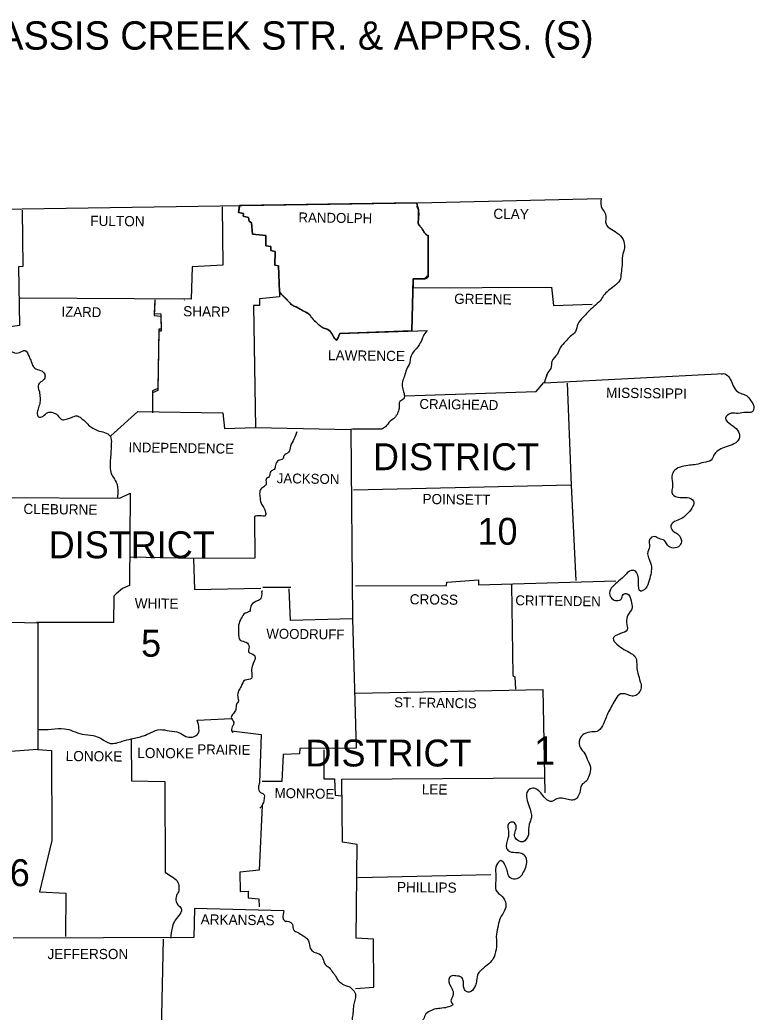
# Model space of a CAD drawing. Extents: x 152 to 3426, y 67 to 2142.
# Drawn here: x 2999.8 to 3303.9, y 1623.7 to 2035 of the extents above; entities that cross this region are included whole.
import ezdxf

# ---------------------------------------------------------------- set-up
doc = ezdxf.new("R2010")
doc.units = 0
for name, color, linetype in [('R_Border', 7, 'Continuous'), ('R_Grid', 7, 'Continuous'), ('S_AREA_CALC', 7, 'Continuous'), ('S_MISC_BOUNDARY', 7, 'Continuous')]:
    doc.layers.add(name, color=color, linetype=linetype)

msp = doc.modelspace()

# ---------------------------------------------------------------- linework, layer by layer
at = {"layer": 'S_AREA_CALC'}
for p, q in [((3090.74, 1958.01), (3163.96, 1959.15)), ((3168.84, 1945.36), (3168.84, 1928.38)), ((3216.98, 1884.51), (3218.15, 1888.13)), ((3217.27, 1885.68), (3218.45, 1888.52)), ((3100.35, 1799.78), (3112, 1799.78))]:
    msp.add_line(p, q, dxfattribs=at)
for points in [[(2703.71, 1956.42), (2861.92, 1956.32), (3000.75, 1956.61), (3164.54, 1959.16), (3240.46, 1960.92)], [(3107.24, 1922.16), (3106.91, 1932.94), (3105.34, 1933.23), (3105.44, 1938.9), (3103.68, 1939.39), (3103.68, 1941.06), (3101.63, 1941.35), (3101.63, 1945.56), (3096.05, 1946.15), (3095.75, 1950.84), (3094.68, 1951.53), (3094.48, 1953.09), (3092.23, 1953.58), (3092.33, 1954.76), (3090.37, 1955.05), (3090.74, 1958.01)], [(3000.75, 1956.03), (3000.95, 1932.74), (2999.28, 1932.64), (2999.58, 1908.28), (2992.73, 1907.3), (2993.32, 1900.75), (2995.66, 1897.71), (2995.47, 1889.98), (2982.16, 1889.5), (2981.67, 1877.56), (2969.54, 1877.17), (2968.95, 1862.69), (2969.64, 1861.51), (2969.93, 1838.42), (2990.87, 1837.05), (2990.58, 1785.49), (3007.21, 1785), (3007.21, 1732.56), (2994.1, 1731.58), (2993.12, 1720.04), (2971.11, 1719.94)], [(3083.62, 1957.49), (3083.82, 1933.23), (3071.1, 1932.55), (3070.71, 1919.24), (2999.97, 1919.63)], [(3090.67, 1957.4), (3090.37, 1955.05), (3092.33, 1954.76), (3092.23, 1953.58), (3094.48, 1953.09), (3094.68, 1951.53), (3095.75, 1950.84), (3096.05, 1946.15), (3101.63, 1945.56), (3101.63, 1941.35), (3103.68, 1941.06), (3103.68, 1939.39), (3105.44, 1938.9), (3105.34, 1933.23), (3106.91, 1932.94), (3107.3, 1920.12), (3098.98, 1919.34), (3099.08, 1916.6), (3096.54, 1916.5), (3097.42, 1866.01), (3136.85, 1865.13), (3137.53, 1786.66), (3111.8, 1785.98), (3111.31, 1799.19)], [(3168.84, 1945.66), (3168.84, 1929.12)], [(3162.68, 1927.56), (3162.16, 1906), (3132.25, 1904.95)], [(3162.19, 1907.11), (3162.68, 1927.56), (3162.68, 1923.94), (3219.91, 1924.23), (3220.7, 1916.6), (3236.84, 1917.18)], [(3055.64, 1918.95), (3055.44, 1913.27), (3058.18, 1913.07), (3058.28, 1906.81), (3057.3, 1906.81), (3056.91, 1882.16), (3054.66, 1881.18), (3054.66, 1872.96)], [(3055.64, 1918.06), (3055.44, 1912.39), (3058.18, 1912.19), (3058.28, 1905.93), (3057.3, 1905.93), (3056.91, 1881.28), (3054.66, 1880.3), (3054.66, 1872.08)], [(3067.87, 1918.75), (3067.97, 1918.85)], [(3132.25, 1904.95), (3168.55, 1906.23)], [(3216.98, 1884.51), (3291.24, 1888.32)], [(3159.25, 1879.12), (3213.55, 1880.89), (3216.78, 1884.6)], [(3226.37, 1884.41), (3228.04, 1842.04), (3229.99, 1802.61)], [(3037.44, 1862.49), (3048.6, 1872.57), (3083.82, 1872.08), (3084.5, 1865.52), (3097.32, 1866.01)], [(3149.67, 1865.33), (3137.73, 1865.33), (3136.85, 1865.13)], [(2990.87, 1837.05), (3041.16, 1836.76), (3045.46, 1838.81), (3045.17, 1800.56), (3042.24, 1799.29), (3039.59, 1797.04), (3038.71, 1796.16), (3038.62, 1785.2), (3006.62, 1785.2)], [(3228.04, 1842.04), (3137.92, 1839.99)], [(3096.93, 1829.03), (3097.12, 1811.81), (3071.69, 1811.71), (3045.56, 1812.2)], [(3071.69, 1811.71), (3072.08, 1798.89), (3099.57, 1799.38)], [(3138.71, 1800.36), (3176.47, 1800.56), (3176.57, 1801.93), (3189.68, 1802.91), (3189.68, 1800.85), (3246.63, 1802.42)], [(3100.35, 1798.11), (3099.86, 1798.01)], [(3203.38, 1800.85), (3203.87, 1763.18), (3204.75, 1762.6), (3205.04, 1757.51)], [(3137.53, 1786.66), (3139, 1733.05), (3115.71, 1732.95), (3115.62, 1730.8), (3108.87, 1730.41), (3108.28, 1719.25), (3100.06, 1719.25)], [(3138.71, 1755.85), (3216.39, 1757.41)], [(3216.39, 1757.41), (3217.18, 1714.56)], [(3073.25, 1744.69), (3087.44, 1745.38)], [(3087.44, 1740.29), (3099.67, 1738.72), (3098.98, 1718.76)], [(3045.86, 1737.06), (3046.05, 1719.55), (3059.85, 1719.25), (3059.95, 1681.68)], [(3007.21, 1732.56), (3012.88, 1732.17), (3012.98, 1694.79), (3007.89, 1673.56), (3018.75, 1673.07), (3018.66, 1655.07)], [(3125.69, 1732.46), (3125.6, 1720.33), (3130.1, 1720.33), (3130.29, 1713.58), (3133.13, 1713.28)], [(3138.71, 1633.54), (3146.34, 1634.03), (3146.24, 1653.9), (3139.1, 1654.38), (3139.49, 1693.23), (3133.33, 1694.11), (3133.13, 1720.23), (3216.59, 1720.82)], [(3100.06, 1709.37), (3098.89, 1682.56), (3090.86, 1681.68), (3091.06, 1673.76), (3094.29, 1673.85), (3094.39, 1671.11), (3098.79, 1670.63), (3098.89, 1667.4)], [(3139.69, 1679.43), (3194.87, 1680.8)], [(3109.06, 1665.64), (3072.08, 1666.61), (3071.88, 1654.58), (2997.03, 1654.29)], [(3059.06, 1653.99), (3058.28, 1616.13), (3071.88, 1615.05)]]:
    msp.add_lwpolyline(points, dxfattribs=at)
for points in [[(3163.96, 1959.15), (3164.16, 1958.7), (3164.34, 1958.24), (3164.65, 1957.32), (3164.85, 1956.38), (3164.88, 1956.15), (3164.91, 1955.91), (3164.93, 1955.44), (3164.92, 1954.78), (3164.89, 1954.12), (3164.85, 1953.46), (3164.83, 1952.8), (3164.82, 1952.49), (3164.77, 1951.57), (3164.76, 1950.96), (3164.78, 1950.66), (3164.8, 1950.5), (3164.82, 1950.43), (3164.83, 1950.35), (3164.91, 1950.11), (3164.96, 1949.99), (3165.03, 1949.88), (3165.19, 1949.67), (3165.37, 1949.48), (3165.76, 1949.09), (3165.94, 1948.9), (3166.1, 1948.69), (3166.42, 1948.18), (3166.72, 1947.66), (3167.03, 1947.14), (3167.2, 1946.88), (3167.37, 1946.63), (3167.59, 1946.39), (3167.83, 1946.16), (3168.08, 1945.96), (3168.84, 1945.36)], [(3164.05, 1957.89), (3164.93, 1955.44), (3164.83, 1952.8), (3164.83, 1950.35), (3166.1, 1948.69), (3167.37, 1946.63), (3168.35, 1945.75)], [(3240.46, 1960.92), (3240.95, 1956.61), (3242.32, 1954.36), (3242.52, 1950.25), (3244.18, 1948.49), (3247.02, 1946.73), (3249.56, 1943.89), (3250.15, 1940.57), (3249.36, 1937.14), (3249.17, 1933.33), (3248.78, 1930), (3248.19, 1926.97), (3245.84, 1924.52), (3243.59, 1922.76), (3241.54, 1920.71), (3240.07, 1918.55), (3237.53, 1916.21), (3234.98, 1913.76), (3232.93, 1911.61), (3230.87, 1908.87), (3229.89, 1905.83), (3227.64, 1903.68), (3225.88, 1901.73), (3223.53, 1899.08), (3222.36, 1896.44), (3220.11, 1893.41), (3219.62, 1890.47), (3218.15, 1888.13), (3218.06, 1887.73)], [(3168.45, 1928.83), (3167.18, 1927.56), (3164.73, 1927.56), (3162.68, 1927.56)], [(3168.84, 1928.38), (3168.66, 1928.21), (3168.47, 1928.05), (3168.07, 1927.79), (3167.63, 1927.62), (3167.41, 1927.57), (3167.29, 1927.56), (3167.18, 1927.56), (3164.73, 1927.56), (3162.68, 1927.56)], [(3132.25, 1904.95), (3132.1, 1904.53), (3131.93, 1904.04), (3131.55, 1903.06), (3131.12, 1902.36), (3130.9, 1902.23), (3130.79, 1902.24), (3130.68, 1902.31), (3130.64, 1902.35), (3130.59, 1902.4), (3130.5, 1902.5), (3130.32, 1902.72), (3129.95, 1903.24), (3129.58, 1903.81), (3129.4, 1904.1), (3129.22, 1904.37), (3128.95, 1904.79), (3128.69, 1905.21), (3128.43, 1905.63), (3128.14, 1906.03), (3127.82, 1906.34), (3127.45, 1906.57), (3126.6, 1906.9), (3125.71, 1907.18), (3124.91, 1907.6), (3124.39, 1907.99), (3123.86, 1908.4), (3123.35, 1908.82), (3122.86, 1909.26), (3121.81, 1910.27), (3120.8, 1911.31), (3120.61, 1911.54), (3120.44, 1911.78), (3120.11, 1912.29), (3119.77, 1912.77), (3119.33, 1913.17), (3119.2, 1913.26), (3119.06, 1913.34), (3118.22, 1913.78), (3117.65, 1914.05), (3117.08, 1914.35), (3115.81, 1915.08), (3114.54, 1915.81), (3114, 1916.08), (3113.44, 1916.31), (3112.89, 1916.56), (3112.39, 1916.89), (3112.26, 1917), (3112.14, 1917.11), (3111.9, 1917.33), (3111.44, 1917.8), (3110.53, 1918.75), (3108.87, 1920.44), (3107.24, 1922.16)], [(3108.38, 1921), (3110.53, 1918.75), (3112.39, 1916.89), (3114.54, 1915.81), (3117.08, 1914.35), (3119.33, 1913.17), (3120.8, 1911.31), (3122.86, 1909.26), (3124.91, 1907.6), (3128.14, 1906.03), (3129.22, 1904.37), (3130.68, 1902.31), (3132.25, 1904.95)], [(3168.25, 1906.13), (3166.79, 1903.78), (3165.61, 1901.04), (3163.26, 1897.91), (3161.5, 1894.88), (3161.21, 1892.82), (3159.84, 1890.08), (3159.06, 1887.34), (3158.18, 1884.99), (3158.18, 1882.55), (3158.86, 1880.1), (3158.67, 1877.85), (3157.2, 1876.78), (3156.81, 1873.94), (3156.22, 1871.98), (3154.95, 1870.03), (3153.09, 1868.56), (3151.13, 1866.31), (3149.67, 1865.33)], [(2995.66, 1897.71), (2999.58, 1897.03), (3001.93, 1897.91), (3003.59, 1895.37), (3004.47, 1893.41), (3005.94, 1890.57), (3008.29, 1889.69), (3010.05, 1888.13), (3010.05, 1886.46), (3008.48, 1884.9), (3007.31, 1883.33), (3007.7, 1881.47), (3008.09, 1878.93), (3008.09, 1876.48), (3007.5, 1874.23), (3007.01, 1872.18), (3007.5, 1870.42), (3009.36, 1870.71), (3011.32, 1872.18), (3013.37, 1872.18), (3015.33, 1871.1), (3017.38, 1869.24), (3019.44, 1869.63), (3021.1, 1870.12), (3023.45, 1870.81), (3025.11, 1869.93), (3026.58, 1868.75), (3028.34, 1866.89), (3030.01, 1865.72), (3032.16, 1864.64), (3034.8, 1863.96), (3037.25, 1862.3), (3037.64, 1859.46), (3037.54, 1857.01), (3037.34, 1853.98), (3037.15, 1850.65), (3037.44, 1847.42), (3038.52, 1845.27), (3039.89, 1842.73), (3040.28, 1840.38), (3040.18, 1836.66)], [(3290.16, 1888.22), (3291.24, 1888.32), (3294.57, 1884.8), (3296.03, 1881.86), (3298.19, 1880.2), (3300.63, 1879.32), (3302.49, 1877.07), (3303.76, 1874.62), (3303.08, 1872.47), (3300.34, 1872.28), (3297.31, 1871.79), (3294.37, 1871.88), (3292.02, 1869.93), (3294.18, 1867.29), (3297.01, 1864.84), (3297.8, 1862.2), (3296.23, 1859.65), (3293.1, 1858.28), (3290.07, 1857.11), (3287.33, 1854.76), (3286.05, 1852.51), (3283.02, 1851.53), (3279.89, 1850.65), (3277.15, 1850.36), (3274.02, 1849.77), (3270.99, 1848.3), (3269.72, 1845.76), (3270.11, 1842.14), (3270.01, 1838.32), (3273.24, 1837.05), (3276.08, 1836.95), (3278.81, 1835.49), (3278.52, 1833.33), (3276.47, 1830.6), (3274.02, 1828.44), (3271.57, 1827.37), (3269.32, 1825.31), (3270.11, 1823.26), (3272.16, 1821.89), (3273.63, 1819.64), (3273.43, 1817.58), (3271.09, 1816.11), (3268.54, 1816.7), (3266.68, 1819.15), (3264.53, 1819.93), (3262.67, 1820.81), (3260.52, 1819.54), (3260.52, 1816.7), (3259.74, 1813.67), (3260.42, 1811.42), (3261.3, 1808.29), (3261.2, 1805.94), (3260.42, 1802.61), (3258.76, 1799.19), (3256.8, 1798.11), (3256.02, 1801.83), (3255.63, 1804.86), (3254.45, 1806.62), (3252.89, 1806.72), (3250.83, 1805.25), (3248.58, 1803), (3245.74, 1800.56), (3244.08, 1798.11), (3244.96, 1795.08), (3247.11, 1794.3), (3248.78, 1794.88), (3249.66, 1796.84), (3251.32, 1797.13), (3252.89, 1794.1)], [(3114.44, 1864.25), (3113.27, 1861.22), (3111.9, 1858.28), (3111.02, 1855.74), (3109.16, 1854.27), (3108.57, 1852.9), (3106.91, 1852.32), (3105.64, 1850.36), (3105.05, 1848.6), (3103.68, 1847.82), (3103, 1845.66), (3101.72, 1844.49), (3101.82, 1842.53), (3100.35, 1841.16), (3099.18, 1839.6), (3099.18, 1837.44), (3099.67, 1834.61), (3100.65, 1832.94), (3101.53, 1830.79), (3101.43, 1829.42), (3098.98, 1829.42), (3096.93, 1829.03)], [(3099.86, 1798.01), (3099.37, 1794.79), (3097.52, 1793.91), (3095.36, 1791.75), (3094.87, 1789.8), (3093.11, 1789.01), (3091.45, 1786.96), (3090.37, 1784.12), (3090.37, 1781.19), (3091.06, 1777.86), (3093.5, 1776.98), (3094.68, 1775.02), (3094.48, 1772.97), (3096.83, 1771.6), (3097.22, 1770.42), (3096.83, 1769.15), (3095.75, 1765.53), (3095.85, 1763.09), (3095.66, 1762.01), (3093.02, 1761.32), (3091.45, 1758.68), (3090.37, 1756.82), (3089.98, 1754.38), (3090.28, 1752.62), (3089.49, 1751.25), (3089.2, 1749.19), (3088.22, 1747.43), (3087.34, 1745.77), (3088.32, 1743.81), (3088.03, 1742.44), (3087.44, 1740.29), (3087.93, 1739.6)], [(3252.89, 1794.1), (3253.28, 1791.26), (3251.62, 1788.23), (3251.03, 1785.2), (3251.32, 1782.16), (3248.19, 1780.5), (3245.45, 1778.54), (3247.02, 1776.2), (3249.95, 1774.04), (3252.89, 1772.38), (3254.75, 1770.72), (3255.24, 1766.71), (3255.72, 1764.16), (3256.7, 1760.64), (3257.09, 1758.19), (3255.33, 1755.26), (3253.28, 1754.67), (3251.13, 1755.36), (3248.58, 1755.55), (3246.53, 1753.59), (3245.06, 1750.86), (3243.59, 1748.12), (3242.52, 1745.77), (3241.44, 1743.22), (3239.29, 1740.29), (3236.65, 1739.8), (3233.51, 1739.02), (3231.66, 1736.86), (3231.95, 1733.24), (3233.71, 1730.8), (3235.08, 1727.76), (3236.06, 1725.12), (3235.57, 1721.8), (3234.2, 1719.35), (3232.44, 1717.88), (3231.66, 1714.75), (3230.38, 1712.4), (3229.21, 1711.62), (3226.86, 1711.82), (3224.32, 1712.31), (3222.16, 1712.11), (3220.11, 1711.03), (3218.06, 1711.72), (3215.9, 1714.07), (3214.14, 1715.83), (3212.19, 1716.51), (3210.13, 1715.44), (3209.74, 1712.21), (3210.72, 1708.88), (3211.6, 1704.38), (3210.72, 1701.64), (3210.42, 1697.14)], [(3007.4, 1740.78), (3012.88, 1740.97), (3018.26, 1741.17), (3021.69, 1740.19), (3025.6, 1738.92), (3030.2, 1738.33), (3033.43, 1737.06), (3037.25, 1735.1), (3042.14, 1735.98), (3045.95, 1736.96), (3050.94, 1738.23), (3054.17, 1739.6), (3057.89, 1740.78), (3061.61, 1740.29), (3065.82, 1739.51), (3068.46, 1737.94), (3073.25, 1738.63), (3073.25, 1744.69)], [(3098.98, 1718.76), (3098.59, 1716.81), (3099.37, 1714.75), (3100.74, 1714.07), (3100.94, 1712.11), (3100.45, 1710.15), (3100.06, 1709.37), (3099.18, 1708.2)], [(3210.42, 1697.14), (3208.17, 1694.3), (3204.85, 1696.06), (3204.85, 1698.41), (3205.34, 1700.86), (3204.16, 1702.42), (3202.11, 1701.74), (3202.11, 1698.71), (3201.91, 1695.77), (3201.32, 1691.56), (3202.69, 1690.29), (3205.83, 1689.9), (3208.08, 1689.31), (3209.45, 1687.06), (3209.35, 1684.32), (3208.27, 1681.68), (3206.71, 1679.53), (3204.26, 1678.75), (3202.3, 1680.02), (3201.52, 1682.56), (3200.64, 1684.81), (3198.98, 1686.48), (3197.22, 1684.62), (3196.82, 1681.19), (3196.92, 1678.26), (3196.92, 1674.25), (3199.47, 1671.6), (3201.03, 1668.57), (3200.54, 1665.83), (3198.68, 1662.6), (3197.9, 1659.77), (3197.12, 1655.95), (3197.22, 1651.74), (3196.53, 1647.63), (3195.16, 1644.89), (3192.62, 1642.64), (3190.95, 1641.18), (3189.58, 1639.71), (3188.9, 1636.77), (3188.41, 1634.72), (3186.55, 1632.27), (3185.08, 1632.08), (3183.91, 1633.05), (3183.52, 1634.72), (3183.52, 1636.38), (3182.74, 1638.04), (3180.29, 1638.73), (3178.33, 1638.63), (3177.45, 1637.26), (3178.72, 1633.45), (3179.21, 1631), (3178.53, 1627.67), (3178.92, 1627.28), (3175.4, 1625.42), (3172.56, 1625.13), (3170.21, 1624.44), (3167.96, 1622.98), (3166.88, 1620.82), (3165.32, 1619.06), (3163.95, 1617.4), (3162.09, 1616.62), (3160.04, 1617.01), (3157.3, 1617.3), (3155.73, 1615.35), (3156.22, 1612.51), (3158.08, 1610.85), (3160.82, 1610.06), (3163.66, 1610.26), (3166.4, 1610.55), (3168.94, 1609.18), (3168.45, 1606.54), (3166, 1605.27), (3162.38, 1604.88), (3159.45, 1605.17), (3155.93, 1604.39), (3154.17, 1602.14), (3155.14, 1598.71), (3158.96, 1597.34), (3160.72, 1594.11), (3160.82, 1591.08), (3159.55, 1587.07), (3157.79, 1585.21), (3154.36, 1584.43), (3151.72, 1583.94), (3151.33, 1579.44), (3150.15, 1577.19), (3148.1, 1576.5), (3145.16, 1577.97), (3143.4, 1578.66), (3141.25, 1579.63), (3138.51, 1581.3), (3136.46, 1581), (3137.04, 1576.7), (3137.24, 1576.5), (3139.59, 1573.27), (3141.94, 1570.73), (3143.01, 1567.7)], [(3059.95, 1681.68), (3062.39, 1680.02), (3064.93, 1678.06), (3065.62, 1675.42), (3065.42, 1673.56), (3064.64, 1672), (3064.45, 1669.55), (3065.62, 1667.79), (3066.7, 1666.32), (3065.62, 1663.68), (3063.76, 1661.23), (3062.78, 1658.49), (3062.1, 1654.38)], [(3109.06, 1665.64), (3109.35, 1661.62), (3111.7, 1661.04), (3112.68, 1659.96), (3113.17, 1657.71), (3114.83, 1656.73), (3117.08, 1655.36), (3118.45, 1654.38), (3119.43, 1652.82), (3120.02, 1650.27), (3121.58, 1648.61), (3123.74, 1647.83), (3125.3, 1645.97), (3126.28, 1643.33), (3127.85, 1642.15), (3129.41, 1640.1), (3130.19, 1639.22), (3131.56, 1636.87), (3132.93, 1635.7), (3133.91, 1635.01), (3135.48, 1634.52), (3137.43, 1633.25), (3138.71, 1631.29), (3138.71, 1629.83), (3138.22, 1627.58), (3137.83, 1625.23), (3137.63, 1622.59), (3137.43, 1620.24), (3138.32, 1618.28), (3137.83, 1615.35), (3136.85, 1613.78), (3136.75, 1611.63), (3136.46, 1608.4), (3136.07, 1606.54), (3135.18, 1603.51), (3133.91, 1601.94)]]:
    msp.add_spline(points, degree=3, dxfattribs=at)
at = {"layer": 'S_MISC_BOUNDARY'}
for p, q in [((3163.96, 1959.15), (3090.74, 1958.01)), ((3168.84, 1928.38), (3168.84, 1945.36))]:
    msp.add_line(p, q, dxfattribs=at)
for points in [[(3090.74, 1958.01), (3090.37, 1955.05), (3092.33, 1954.76), (3092.23, 1953.58), (3094.48, 1953.09), (3094.68, 1951.53), (3095.75, 1950.84), (3096.05, 1946.15), (3101.63, 1945.56), (3101.63, 1941.35), (3103.68, 1941.06), (3103.68, 1939.39), (3105.44, 1938.9), (3105.34, 1933.23), (3106.91, 1932.94), (3107.24, 1922.16)], [(3132.25, 1904.95), (3162.16, 1906), (3162.68, 1927.56)]]:
    msp.add_lwpolyline(points, dxfattribs=at)
for points in [[(3164.77, 1951.58), (3164.82, 1952.49), (3164.83, 1952.8), (3164.85, 1953.46), (3164.89, 1954.12), (3164.92, 1954.78), (3164.93, 1955.44), (3164.91, 1955.91), (3164.88, 1956.15), (3164.85, 1956.38), (3164.65, 1957.32), (3164.34, 1958.24), (3164.16, 1958.7), (3163.96, 1959.15)], [(3168.84, 1945.36), (3168.08, 1945.96), (3167.83, 1946.16), (3167.59, 1946.39), (3167.37, 1946.63), (3167.2, 1946.88), (3167.03, 1947.14), (3166.72, 1947.66), (3166.42, 1948.18), (3166.1, 1948.69), (3165.94, 1948.9), (3165.76, 1949.09), (3165.37, 1949.48), (3165.19, 1949.67), (3165.03, 1949.88), (3164.96, 1949.99), (3164.91, 1950.11), (3164.83, 1950.35), (3164.82, 1950.43), (3164.8, 1950.5), (3164.78, 1950.66), (3164.76, 1950.96), (3164.77, 1951.57), (3164.77, 1951.58)], [(3162.68, 1927.56), (3164.73, 1927.56), (3167.18, 1927.56), (3167.29, 1927.56), (3167.41, 1927.57), (3167.63, 1927.62), (3168.07, 1927.79), (3168.47, 1928.05), (3168.66, 1928.21), (3168.84, 1928.38)], [(3107.24, 1922.16), (3108.87, 1920.44), (3110.53, 1918.75), (3111.44, 1917.8), (3111.9, 1917.33), (3112.14, 1917.11), (3112.26, 1917), (3112.39, 1916.89), (3112.89, 1916.56), (3113.44, 1916.31), (3114, 1916.08), (3114.54, 1915.81), (3115.81, 1915.08), (3117.08, 1914.35), (3117.65, 1914.05), (3118.22, 1913.78), (3119.06, 1913.34), (3119.2, 1913.26), (3119.33, 1913.17), (3119.77, 1912.77), (3120.11, 1912.29), (3120.44, 1911.78), (3120.6, 1911.55)], [(3120.6, 1911.55), (3120.61, 1911.54), (3120.8, 1911.31), (3121.81, 1910.27), (3122.86, 1909.26), (3123.35, 1908.82), (3123.86, 1908.4), (3124.39, 1907.99), (3124.91, 1907.6), (3125.71, 1907.18), (3125.93, 1907.11), (3126.16, 1907.04), (3126.38, 1906.97), (3126.6, 1906.9), (3127.45, 1906.57), (3127.82, 1906.34), (3128.14, 1906.03), (3128.43, 1905.63), (3128.69, 1905.21), (3128.95, 1904.79), (3129.22, 1904.37), (3129.4, 1904.1), (3129.58, 1903.81), (3129.95, 1903.24), (3130.32, 1902.72), (3130.5, 1902.5), (3130.59, 1902.4), (3130.64, 1902.35), (3130.68, 1902.31), (3130.79, 1902.24), (3130.9, 1902.23), (3131.02, 1902.28), (3131.12, 1902.36), (3131.26, 1902.53), (3131.37, 1902.7), (3131.47, 1902.87), (3131.55, 1903.06), (3131.93, 1904.04), (3132.1, 1904.53), (3132.25, 1904.95)]]:
    msp.add_spline(points, degree=3, dxfattribs=at)

# ---------------------------------------------------------------- texts
at = {"layer": 'R_Border'}
for s, height, p in [('EASSIS CREEK STR. & APPRS. (S)', 11.724, (2980.36, 2022.61)), ('JEFFERSON', 4.207, (3011.22, 1645.68))]:
    msp.add_text(s, height=height, dxfattribs=at).set_placement(p)
for s, height, rotation, p in [('FULTON', 4.206, 359.4996, (3028.93, 1949.57)), ('RANDOLPH', 4.109, 359.2583, (3115.13, 1951.04)), ('CLAY', 4.206, 359.2258, (3195.85, 1952.5)), ('GREENE', 4.207, 359.2361, (3179.6, 1917.28)), ('IZARD', 4.108, 358.9258, (3016.99, 1912)), ('SHARP', 4.206, 359.3905, (3067.38, 1912.1)), ('LAWRENCE', 4.207, 359.2678, (3127.36, 1893.9)), ('MISSISSIPPI', 4.2062, 359.3097, (3242.52, 1878.34)), ('CRAIGHEAD', 4.109, 359.1159, (3165.22, 1873.74)), ('INDEPENDENCE', 4.1081, 359.2187, (3044.78, 1855.74)), ('JACKSON', 4.108, 359.1352, (3106.13, 1842.92)), ('POINSETT', 4.206, 359.1987, (3166.49, 1834.31)), ('CLEBURNE', 4.206, 359.2535, (3001.24, 1830.2)), ('WHITE', 4.207, 359.3139, (3047.32, 1791.07)), ('CROSS', 4.206, 359.3839, (3161.21, 1792.73)), ('CRITTENDEN', 4.109, 359.213, (3204.94, 1792.34)), ('WOODRUFF', 4.108, 359.2748, (3101.82, 1778.54)), ('ST. FRANCIS', 4.1081, 359.2216, (3154.75, 1750.07)), ('LONOKE', 4.207, 359.4974, (3018.75, 1727.76)), ('LONOKE', 4.207, 359.4974, (3048.4, 1729.04)), ('PRAIRIE', 4.109, 359.2116, (3073.25, 1730.6)), ('MONROE', 4.108, 359.0331, (3105.25, 1712.5)), ('LEE', 4.207, 359.4327, (3166.2, 1713.97)), ('PHILLIPS', 4.206, 359.3179, (3155.93, 1673.46)), ('ARKANSAS', 4.206, 359.2678, (3074.62, 1660.06))]:
    msp.add_text(s, height=height, rotation=rotation, dxfattribs=at).set_placement(p)
at = {"layer": 'R_Grid'}
for s, height, p in [('DISTRICT', 11.154, (3146, 1848.31)), ('10', 11.154, (3189.29, 1817.39)), ('DISTRICT', 11.154, (3011.71, 1811.81)), ('5', 11.15, (3049.97, 1771.01)), ('DISTRICT', 11.154, (3118.06, 1725.51)), ('DISTRICT 6', 11.154, (2922.67, 1675.91))]:
    msp.add_text(s, height=height, dxfattribs=at).set_placement(p)
at = {"layer": 'S_AREA_CALC'}
msp.add_text('1', height=11.74, dxfattribs=at).set_placement((3212.77, 1726.2))

doc.saveas('drawing.dxf')
